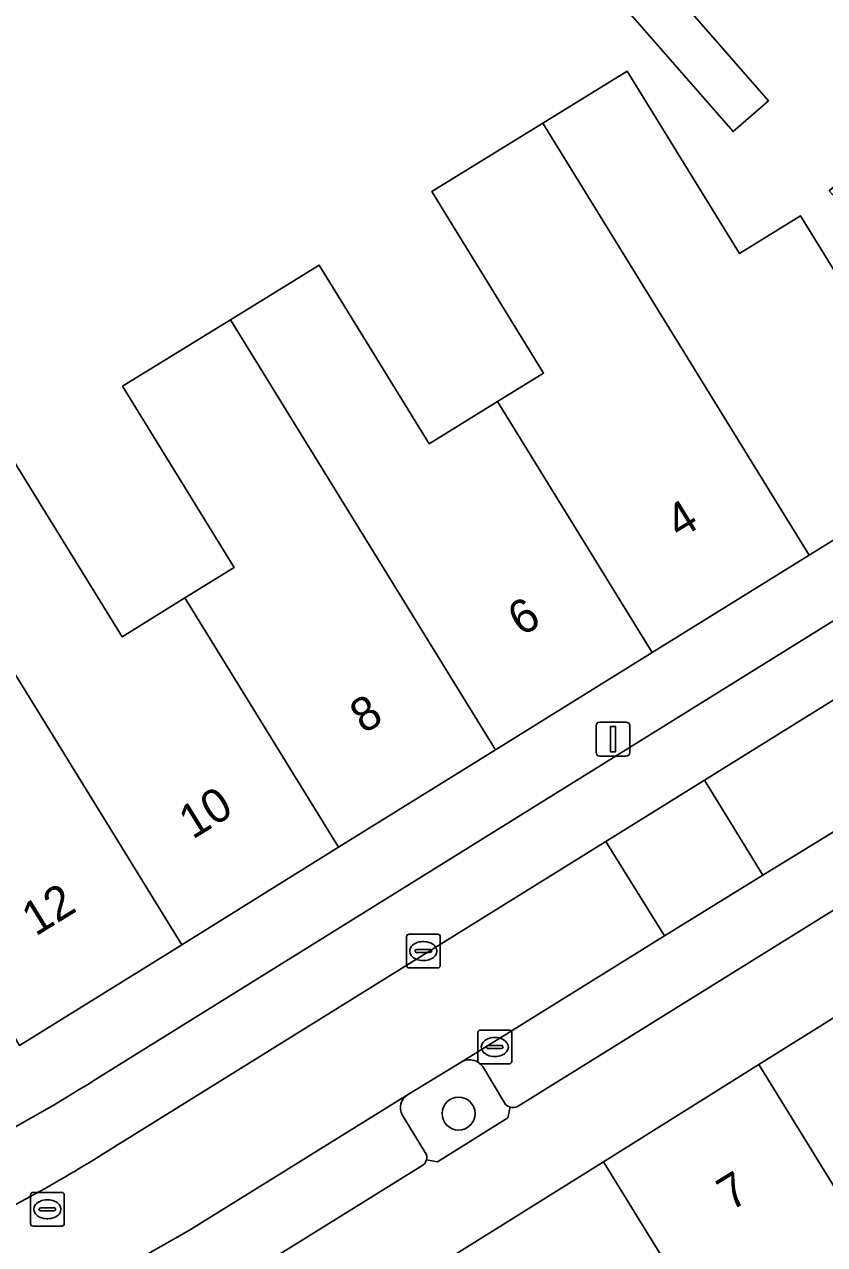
# Model space of a CAD drawing. Extents: x 159716 to 160783, y 383290 to 384031.
# Drawn here: x 160474.83 to 160498.53, y 383488.74 to 383524.87 of the extents above; entities that cross this region are included whole.
import ezdxf

# ---------------------------------------------------------------- set-up
doc = ezdxf.new("R2010")
doc.units = 0
for name, color, linetype in [('IMGEO_Boom', 7, 'Continuous'), ('IMGEO_Erf', 7, 'Continuous'), ('IMGEO_Groenvoorziening', 7, 'Continuous'), ('IMGEO_Kolk', 7, 'Continuous'), ('IMGEO_Lichtmast', 7, 'Continuous'), ('IMGEO_Pand', 7, 'Continuous'), ('IMGEO_Pand_nummerreeks', 7, 'Continuous'), ('IMGEO_Parkeervlak_open', 7, 'Continuous'), ('IMGEO_Rijbaan_lokaal_open', 7, 'Continuous'), ('IMGEO_Rioolput', 7, 'Continuous'), ('IMGEO_Voetpad_open', 7, 'Continuous')]:
    doc.layers.add(name, color=color, linetype=linetype)

msp = doc.modelspace()

# ---------------------------------------------------------------- linework, layer by layer
at = {"layer": 'IMGEO_Boom'}
msp.add_circle((160487.689, 383492.619), 0.489, dxfattribs=at)
at = {"layer": 'IMGEO_Erf'}
for points in [[(160484.757, 383536.467), (160496.862, 383522.603), (160495.817, 383521.691), (160482.143, 383537.339)], [(160474.442, 383512.059), (160477.722, 383506.738), (160479.584, 383507.886), (160481.047, 383508.788), (160477.74, 383514.152), (160480.93, 383516.118), (160483.558, 383517.738), (160486.817, 383512.452), (160488.841, 383513.7), (160490.206, 383514.541), (160486.892, 383519.915), (160490.181, 383521.943), (160492.677, 383523.481), (160496.006, 383518.081), (160497.813, 383519.195), (160502.361, 383511.817), (160503.371, 383512.413), (160504.529, 383513.509), (160498.663, 383519.938), (160500, 383521.105), (160502.393, 383523.195), (160504.587, 383525.045), (160505.499, 383524.004), (160507.373, 383525.646)]]:
    msp.add_lwpolyline(points, dxfattribs=at)
at = {"layer": 'IMGEO_Groenvoorziening'}
for points in [[(160487.816, 383494.171), (160486.172, 383493.171)], [(160489.05, 383492.936), (160488.407, 383494.011)], [(160486.739, 383491.248), (160487.068, 383491.194), (160489.145, 383492.498), (160489.214, 383492.808)], [(160486.014, 383492.584), (160486.703, 383491.465)]]:
    msp.add_lwpolyline(points, dxfattribs=at)
for centre, radius, start, end in [((160488.012, 383493.723), 0.489, 36.078, 113.6252), ((160486.426, 383492.788), 0.46, 123.5379, 206.3321), ((160489.292, 383493.077), 0.281, 210.2649, 253.7919), ((160486.476, 383491.316), 0.272, 345.5339, 33.3051)]:
    msp.add_arc(centre, radius, start, end, dxfattribs=at)
at = {"layer": 'IMGEO_Kolk'}
for p, q in [((160486.145, 383497.006), (160486.145, 383497.858)), ((160486.22, 383497.932), (160487.072, 383497.932)), ((160487.146, 383497.858), (160487.146, 383497.006)), ((160486.404, 383497.426), (160486.404, 383497.438)), ((160486.842, 383497.389), (160486.444, 383497.389)), ((160486.447, 383497.475), (160486.845, 383497.475)), ((160486.633, 383497.712), (160486.658, 383497.712)), ((160486.888, 383497.438), (160486.888, 383497.426)), ((160486.656, 383497.152), (160486.631, 383497.152)), ((160487.072, 383496.932), (160486.22, 383496.932)), ((160488.26, 383494.165), (160488.26, 383495.017)), ((160488.335, 383495.091), (160489.187, 383495.091)), ((160488.748, 383494.871), (160488.773, 383494.871)), ((160489.261, 383495.017), (160489.261, 383494.165)), ((160488.519, 383494.585), (160488.519, 383494.597)), ((160488.957, 383494.548), (160488.559, 383494.548)), ((160488.562, 383494.634), (160488.96, 383494.634)), ((160489.003, 383494.597), (160489.003, 383494.585)), ((160488.771, 383494.311), (160488.746, 383494.311)), ((160489.187, 383494.091), (160488.335, 383494.091))]:
    msp.add_line(p, q, dxfattribs=at)
for points in [[(160486.145, 383497.006), (160486.145, 383497.858)], [(160486.22, 383497.932), (160487.072, 383497.932)], [(160487.146, 383497.858), (160487.146, 383497.006)], [(160487.072, 383496.932), (160486.22, 383496.932)], [(160488.26, 383494.165), (160488.26, 383495.017)], [(160488.335, 383495.091), (160489.187, 383495.091)], [(160489.261, 383495.017), (160489.261, 383494.165)], [(160489.187, 383494.091), (160488.335, 383494.091)]]:
    msp.add_lwpolyline(points, dxfattribs=at)
for centre, radius, start, end in [((160486.222, 383497.856), 0.0765, 91.552, 178.448), ((160486.222, 383497.856), 0.0765, 91.552, 178.448), ((160487.07, 383497.856), 0.0765, 1.552, 88.448), ((160487.07, 383497.856), 0.0765, 1.552, 88.448), ((160486.444, 383497.435), 0.0403, 85.8775, 175.7526), ((160486.441, 383497.425), 0.0366, 178.938, 274.7102), ((160486.845, 383497.432), 0.043, 264.8664, 352.4533), ((160486.849, 383497.437), 0.0386, 1.7309, 96.639), ((160486.222, 383497.008), 0.0765, 181.552, 268.448), ((160486.222, 383497.008), 0.0765, 181.552, 268.448), ((160487.07, 383497.008), 0.0765, 271.552, 358.448), ((160487.07, 383497.008), 0.0765, 271.552, 358.448), ((160488.337, 383495.015), 0.0765, 91.552, 178.448), ((160488.337, 383495.015), 0.0765, 91.552, 178.448), ((160489.185, 383495.015), 0.0765, 1.552, 88.448), ((160489.185, 383495.015), 0.0765, 1.552, 88.448), ((160488.559, 383494.594), 0.0403, 85.8775, 175.7526), ((160488.556, 383494.584), 0.0366, 178.938, 274.7102), ((160488.96, 383494.591), 0.043, 264.8664, 352.4533), ((160488.964, 383494.596), 0.0386, 1.7309, 96.639), ((160488.337, 383494.167), 0.0765, 181.552, 268.448), ((160488.337, 383494.167), 0.0765, 181.552, 268.448), ((160489.185, 383494.167), 0.0765, 271.552, 358.448), ((160489.185, 383494.167), 0.0765, 271.552, 358.448)]:
    msp.add_arc(centre, radius, start, end, dxfattribs=at)
for centre, major_axis, ratio, start_param, end_param in [((160486.632, 383497.432), (-0.387, 0.002), 0.722429, 4.712389, 7.853982), ((160486.657, 383497.432), (-0.39, 0.002), 0.717154, 1.570796, 4.712389), ((160488.747, 383494.591), (-0.387, 0.002), 0.722429, 4.712389, 7.853982), ((160488.772, 383494.591), (-0.39, 0.002), 0.717154, 1.570796, 4.712389)]:
    msp.add_ellipse(centre, major_axis=major_axis, ratio=ratio, start_param=start_param, end_param=end_param, dxfattribs=at)
at = {"layer": 'IMGEO_Lichtmast'}
for p, q in [((160491.765, 383503.305), (160491.765, 383504.105)), ((160491.765, 383504.105), (160491.765, 383503.305)), ((160491.865, 383504.205), (160492.655, 383504.205)), ((160492.655, 383504.205), (160491.865, 383504.205)), ((160492.755, 383504.105), (160492.755, 383503.305)), ((160492.755, 383503.305), (160492.755, 383504.105)), ((160492.655, 383503.205), (160491.865, 383503.205)), ((160491.865, 383503.205), (160492.655, 383503.205))]:
    msp.add_line(p, q, dxfattribs=at)
msp.add_lwpolyline([(160492.185, 383504.08), (160492.335, 383504.08), (160492.335, 383503.33), (160492.185, 383503.33), (160492.185, 383504.08)], dxfattribs=at)
for centre, start, end in [((160491.865, 383504.105), 90, 180), ((160491.865, 383504.105), 90, 180), ((160492.655, 383504.105), 0, 90), ((160492.655, 383504.105), 360, 90), ((160491.865, 383503.305), 180, 270), ((160491.865, 383503.305), 180, 270), ((160492.655, 383503.305), 270, 0), ((160492.655, 383503.305), 270, 0)]:
    msp.add_arc(centre, 0.1, start, end, dxfattribs=at)
at = {"layer": 'IMGEO_Pand'}
for points in [[(160497.813, 383519.195), (160496.006, 383518.081), (160492.677, 383523.481), (160490.181, 383521.943), (160498.066, 383509.151), (160502.361, 383511.817)], [(160490.181, 383521.943), (160486.892, 383519.915), (160490.206, 383514.541), (160488.841, 383513.7), (160493.423, 383506.269), (160498.066, 383509.151)], [(160488.841, 383513.7), (160486.817, 383512.452), (160483.558, 383517.738), (160480.93, 383516.118), (160488.779, 383503.386), (160493.423, 383506.269)], [(160480.93, 383516.118), (160477.74, 383514.152), (160481.047, 383508.788), (160479.584, 383507.886), (160484.135, 383500.503), (160488.779, 383503.386)], [(160479.584, 383507.886), (160477.722, 383506.738), (160474.442, 383512.059), (160471.651, 383510.339), (160478.024, 383500), (160479.491, 383497.62), (160484.135, 383500.503)], [(160471.651, 383510.339), (160468.666, 383508.499), (160471.973, 383503.136), (160470.216, 383502.033), (160471.464, 383500), (160472.137, 383498.904), (160474.684, 383494.636), (160479.491, 383497.62), (160478.024, 383500)], [(160505.742, 383489.533), (160501.178, 383496.945), (160496.58, 383494.069), (160500, 383488.516), (160504.391, 383481.385), (160504.71, 383481.58), (160507.444, 383483.258), (160504.18, 383488.574)], [(160500, 383488.516), (160496.58, 383494.069), (160491.982, 383491.194), (160496.493, 383483.868), (160498.462, 383485.076), (160500, 383482.559), (160501.719, 383479.746), (160502.854, 383480.442), (160504.391, 383481.385)], [(160496.493, 383483.868), (160491.982, 383491.194), (160487.383, 383488.318), (160495.196, 383475.63), (160498.39, 383477.59), (160495.073, 383482.997)]]:
    msp.add_lwpolyline(points, close=True, dxfattribs=at)
at = {"layer": 'IMGEO_Parkeervlak_open'}
for points in [[(160492.049, 383500.676), (160494.972, 383502.492), (160504.828, 383508.614), (160506.49, 383509.69), (160507.743, 383510.567), (160508.401, 383511.054)], [(160502.461, 383509.473), (160499.497, 383507.648), (160476.969, 383493.644)], [(160503.249, 383503.69), (160496.699, 383499.682), (160493.79, 383497.878), (160487.816, 383494.171)], [(160489.45, 383492.842), (160503.826, 383501.773)], [(160477.732, 383491.785), (160492.049, 383500.676)], [(160488.407, 383494.011), (160489.05, 383492.936)], [(160486.172, 383493.171), (160479.723, 383489.166), (160477.633, 383487.98), (160475.827, 383486.951), (160470.424, 383484.097)], [(160486.703, 383491.465), (160486.014, 383492.584)], [(160471.977, 383482.658), (160475.102, 383484.288), (160475.759, 383484.63), (160475.813, 383484.659), (160477.273, 383485.42), (160478.649, 383486.162), (160479.757, 383486.826), (160480.657, 383487.387), (160486.63, 383491.095)]]:
    msp.add_lwpolyline(points, dxfattribs=at)
for centre, radius, start, end in [((160488.012, 383493.723), 0.489, 36.078, 113.6252), ((160446.37, 383542.755), 57.863, 297.1492, 301.92492), ((160486.426, 383492.788), 0.46, 123.5379, 206.3321), ((160489.292, 383493.077), 0.281, 210.2649, 253.7919), ((160489.295, 383493.079), 0.283, 253.3129, 303.0833), ((160453.227, 383529.801), 45.229, 296.04, 302.8053), ((160486.474, 383491.322), 0.275, 304.598, 344.4684), ((160486.476, 383491.316), 0.272, 345.5339, 33.3051)]:
    msp.add_arc(centre, radius, start, end, dxfattribs=at)
at = {"layer": 'IMGEO_Rijbaan_lokaal_open'}
for points in [[(160522.412, 383522.964), (160517.242, 383518.592), (160508.401, 383511.054), (160507.743, 383510.567), (160506.49, 383509.69), (160504.828, 383508.614), (160494.972, 383502.492), (160496.699, 383499.682), (160503.249, 383503.69), (160503.456, 383503.817), (160505.032, 383504.834), (160508.822, 383507.344), (160510.556, 383508.571), (160519.442, 383516.111), (160524.466, 383520.413)], [(160494.972, 383502.492), (160492.049, 383500.676), (160493.79, 383497.878), (160496.699, 383499.682)]]:
    msp.add_lwpolyline(points, close=True, dxfattribs=at)
for points in [[(160486.172, 383493.171), (160487.816, 383494.171), (160493.79, 383497.878), (160492.049, 383500.676), (160477.732, 383491.785)], [(160444.425, 383474.364), (160442.414, 383473.513), (160443.698, 383470.478), (160444.194, 383470.688), (160446.383, 383471.66), (160448.326, 383472.59), (160450.686, 383473.825), (160452.428, 383474.705), (160468.689, 383483.205), (160470.424, 383484.097), (160475.827, 383486.951), (160477.633, 383487.98), (160479.723, 383489.166), (160486.172, 383493.171)]]:
    msp.add_lwpolyline(points, dxfattribs=at)
msp.add_arc((160453.227, 383529.801), 45.229, 296.04, 302.8053, dxfattribs=at)
at = {"layer": 'IMGEO_Rioolput'}
for p, q in [((160475.011, 383489.362), (160475.011, 383490.214)), ((160475.086, 383490.288), (160475.938, 383490.288)), ((160476.012, 383490.214), (160476.012, 383489.362)), ((160475.27, 383489.782), (160475.27, 383489.794)), ((160475.313, 383489.831), (160475.711, 383489.831)), ((160475.499, 383490.068), (160475.524, 383490.068)), ((160475.754, 383489.794), (160475.754, 383489.782)), ((160475.708, 383489.745), (160475.31, 383489.745)), ((160475.522, 383489.508), (160475.497, 383489.508)), ((160475.938, 383489.288), (160475.086, 383489.288))]:
    msp.add_line(p, q, dxfattribs=at)
for points in [[(160475.011, 383489.362), (160475.011, 383490.214)], [(160475.086, 383490.288), (160475.938, 383490.288)], [(160476.012, 383490.214), (160476.012, 383489.362)], [(160475.938, 383489.288), (160475.086, 383489.288)]]:
    msp.add_lwpolyline(points, dxfattribs=at)
for centre, radius, start, end in [((160475.088, 383490.212), 0.0765, 91.552, 178.448), ((160475.088, 383490.212), 0.0765, 91.552, 178.448), ((160475.936, 383490.212), 0.0765, 1.552, 88.448), ((160475.936, 383490.212), 0.0765, 1.552, 88.448), ((160475.31, 383489.791), 0.0403, 85.8775, 175.7526), ((160475.307, 383489.781), 0.0366, 178.938, 274.7102), ((160475.711, 383489.788), 0.043, 264.8664, 352.4533), ((160475.715, 383489.793), 0.0386, 1.7309, 96.639), ((160475.088, 383489.364), 0.0765, 181.552, 268.448), ((160475.088, 383489.364), 0.0765, 181.552, 268.448), ((160475.936, 383489.364), 0.0765, 271.552, 358.448), ((160475.936, 383489.364), 0.0765, 271.552, 358.448)]:
    msp.add_arc(centre, radius, start, end, dxfattribs=at)
for centre, major_axis, ratio, start_param, end_param in [((160475.498, 383489.788), (-0.387, 0.002), 0.722429, 4.712389, 7.853982), ((160475.523, 383489.788), (-0.39, 0.002), 0.717154, 1.570796, 4.712389)]:
    msp.add_ellipse(centre, major_axis=major_axis, ratio=ratio, start_param=start_param, end_param=end_param, dxfattribs=at)
at = {"layer": 'IMGEO_Voetpad_open'}
for points in [[(160482.143, 383537.339), (160495.817, 383521.691), (160496.862, 383522.603), (160484.757, 383536.467)], [(160519.644, 383526.744), (160513.093, 383521.008), (160513.021, 383521.09), (160510.208, 383518.63), (160510.281, 383518.547), (160504.529, 383513.509), (160503.371, 383512.413), (160502.361, 383511.817), (160498.066, 383509.151), (160493.423, 383506.269), (160488.779, 383503.386), (160484.135, 383500.503), (160479.491, 383497.62), (160474.684, 383494.636)], [(160432.435, 383460.679), (160437.405, 383462.822), (160442.373, 383464.964), (160447.343, 383467.106), (160452.408, 383469.29), (160453.253, 383469.701), (160457.967, 383472.21), (160462.733, 383474.747), (160467.502, 383477.285), (160472.268, 383479.822), (160477.037, 383482.36), (160478.241, 383483.001), (160480.377, 383484.144), (160482.026, 383485.026), (160482.856, 383485.488), (160487.383, 383488.318), (160491.982, 383491.194), (160496.58, 383494.069), (160501.178, 383496.945), (160505.777, 383499.821), (160510.513, 383502.782), (160513.025, 383504.314), (160521.892, 383510.886), (160528.836, 383516.141)], [(160476.969, 383493.644), (160499.497, 383507.648), (160502.461, 383509.473)], [(160503.826, 383501.773), (160489.45, 383492.842)], [(160489.214, 383492.808), (160489.145, 383492.498), (160487.068, 383491.194), (160486.739, 383491.248)], [(160486.63, 383491.095), (160480.657, 383487.387), (160479.757, 383486.826), (160478.649, 383486.162), (160477.273, 383485.42), (160475.813, 383484.659), (160475.759, 383484.63), (160475.102, 383484.288), (160471.977, 383482.658)]]:
    msp.add_lwpolyline(points, dxfattribs=at)
for centre, radius, start, end in [((160446.37, 383542.755), 57.863, 297.1492, 301.92492), ((160489.295, 383493.079), 0.283, 253.3129, 303.0833), ((160486.474, 383491.322), 0.275, 304.598, 344.4684)]:
    msp.add_arc(centre, radius, start, end, dxfattribs=at)

# ---------------------------------------------------------------- texts
at = {"layer": 'IMGEO_Pand_nummerreeks'}
for s, rotation, p in [('4', 31.6502, (160494.232, 383509.61)), ('6', 31.6502, (160489.555, 383506.727)), ('8', 31.6502, (160484.881, 383503.846)), ('10', 31.6502, (160479.812, 383500.722)), ('12', 31.6502, (160475.162, 383497.855)), ('7', 31.5929, (160495.749, 383489.719))]:
    msp.add_text(s, height=1, rotation=rotation, dxfattribs=at).set_placement(p)

doc.saveas('drawing.dxf')
